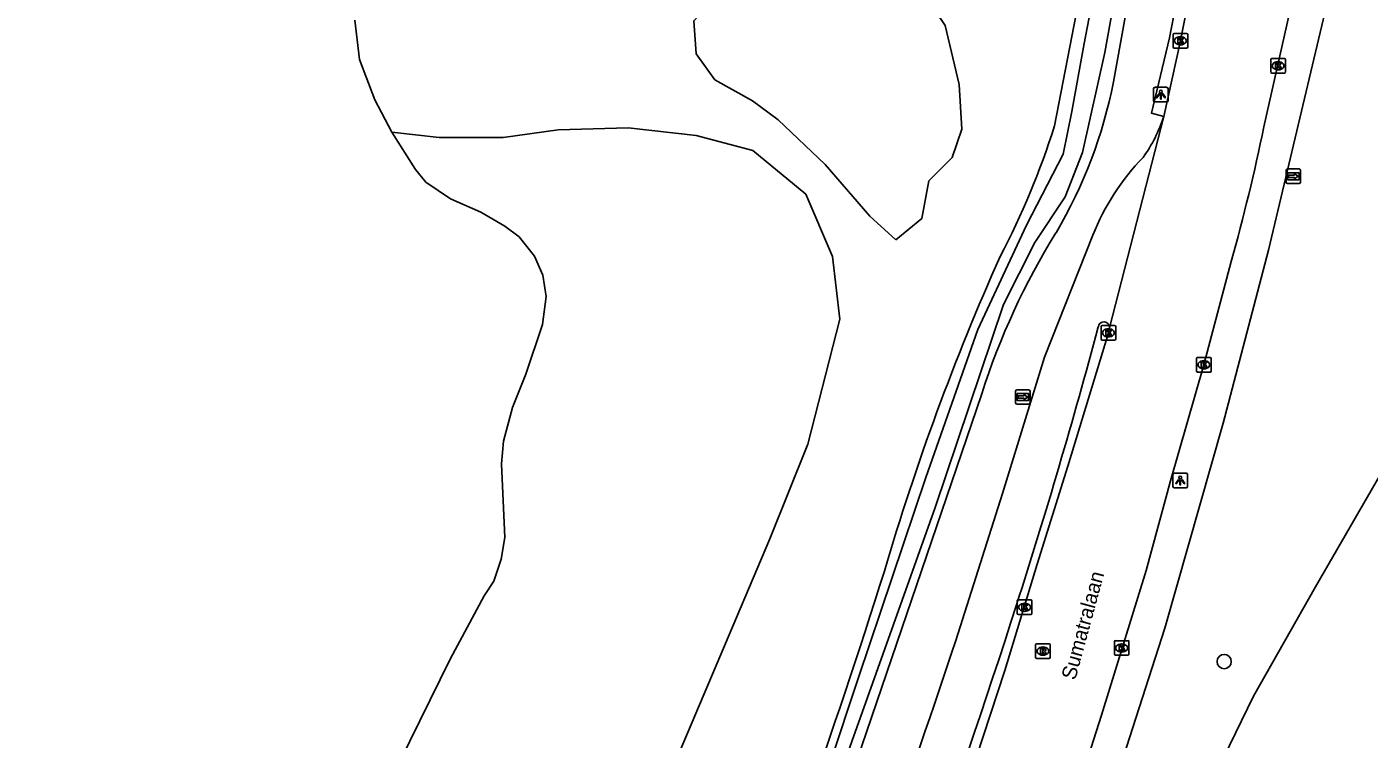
# Model space of a CAD drawing. Extents: x 162417 to 163721, y 384268 to 385416.
# Drawn here: x 162743.5 to 162835.2, y 385301.4 to 385350.1 of the extents above; entities that cross this region are included whole.
import ezdxf

# ---------------------------------------------------------------- set-up
doc = ezdxf.new("R2010")
doc.units = 0
for name, color, linetype in [('IMGEO_Boom', 7, 'Continuous'), ('IMGEO_Fietspad_gesloten', 7, 'Continuous'), ('IMGEO_Gemengd_bos', 7, 'Continuous'), ('IMGEO_Groenvoorziening', 7, 'Continuous'), ('IMGEO_Kolk', 7, 'Continuous'), ('IMGEO_Lichtpunt', 7, 'Continuous'), ('IMGEO_Loofbos', 7, 'Continuous'), ('IMGEO_Openbare_ruimte_label', 7, 'Continuous'), ('IMGEO_Rietland', 7, 'Continuous'), ('IMGEO_Rijbaan_lokaal_open', 7, 'Continuous'), ('IMGEO_Rioolput', 7, 'Continuous'), ('IMGEO_Voetpad_open', 7, 'Continuous'), ('IMGEO_Waterloop', 7, 'Continuous'), ('IMGEO_Wegwijzer', 7, 'Continuous')]:
    doc.layers.add(name, color=color, linetype=linetype)

msp = doc.modelspace()

# ---------------------------------------------------------------- linework, layer by layer
at = {"layer": 'IMGEO_Boom'}
msp.add_circle((162825.334, 385306.727), 0.489, dxfattribs=at)
at = {"layer": 'IMGEO_Fietspad_gesloten'}
msp.add_lwpolyline([(162816.367, 385335.842), (162813.052, 385327.519), (162810.185, 385318.215), (162807.009, 385308.175)], dxfattribs=at)
for centre, radius, start, end in [((162811.055, 385347.283), 10.681, 325.03841, 341.83149), ((162831.08, 385330.1), 15.794, 135.53739, 158.68249), ((162410.819, 385438.792), 420.352, 342.24558, 344.94099), ((162817.12, 385329.544), 0.385, 355.3852, 174.79122), ((162215.588, 385502.359), 625.67, 338.291039, 342.153446), ((162026.4, 385569.306), 823.128, 339.426761, 341.503782)]:
    msp.add_arc(centre, radius, start, end, dxfattribs=at)
at = {"layer": 'IMGEO_Gemengd_bos'}
msp.add_lwpolyline([(162814.913, 385263.725), (162814.61, 385265.935), (162814.59, 385269.784), (162815.131, 385272.835), (162815.951, 385276.063), (162817.275, 385280.881), (162819.108, 385286.107), (162824.458, 385298.467), (162827.331, 385304.355), (162831.573, 385311.834), (162853.395, 385349.579)], dxfattribs=at)
at = {"layer": 'IMGEO_Groenvoorziening'}
for points in [[(162817.771, 385346.314), (162823.818, 385379.783)], [(162820.255, 385376.893), (162813.74, 385343.308)], [(162743.529, 385195.341), (162794.303, 385315.112), (162796.888, 385321.578), (162799.085, 385330.113), (162798.568, 385334.381), (162796.759, 385338.648), (162793.14, 385341.623), (162789.264, 385342.657), (162784.611, 385343.175), (162779.83, 385343.045), (162776.082, 385342.528), (162771.689, 385342.528), (162768.457, 385342.888)], [(162796.119, 385287.884), (162808.773, 385325.013)]]:
    msp.add_lwpolyline(points, dxfattribs=at)
for centre, radius, start, end in [((162785.841, 385352.589), 32.541, 329.37861, 348.88148), ((162760.787, 385360.126), 55.56, 332.40245, 342.38062), ((162855.966, 385309.928), 49.546, 148.23055, 162.27401), ((162964.427, 385265.402), 169.112, 155.92544, 163.68346), ((162281.566, 385477.839), 546.061, 338.77326, 342.42056)]:
    msp.add_arc(centre, radius, start, end, dxfattribs=at)
at = {"layer": 'IMGEO_Kolk'}
for p, q in [((162821.841, 385348.7), (162821.841, 385349.552)), ((162821.916, 385349.626), (162822.768, 385349.626)), ((162822.352, 385348.846), (162822.327, 385348.846)), ((162822.329, 385349.406), (162822.354, 385349.406)), ((162822.842, 385349.552), (162822.842, 385348.7)), ((162822.768, 385348.626), (162821.916, 385348.626)), ((162828.593, 385347.917), (162829.445, 385347.917)), ((162828.518, 385346.991), (162828.518, 385347.843)), ((162829.029, 385347.137), (162829.004, 385347.137)), ((162829.006, 385347.697), (162829.031, 385347.697)), ((162829.519, 385347.843), (162829.519, 385346.991)), ((162829.445, 385346.917), (162828.593, 385346.917)), ((162816.92, 385328.752), (162816.92, 385329.604)), ((162816.995, 385329.678), (162817.847, 385329.678)), ((162817.921, 385329.604), (162817.921, 385328.752)), ((162817.847, 385328.678), (162816.995, 385328.678)), ((162817.431, 385328.898), (162817.406, 385328.898)), ((162817.408, 385329.458), (162817.433, 385329.458)), ((162823.446, 385326.573), (162823.446, 385327.425)), ((162823.521, 385327.499), (162824.373, 385327.499)), ((162823.934, 385327.279), (162823.959, 385327.279)), ((162824.447, 385327.425), (162824.447, 385326.573)), ((162824.373, 385326.499), (162823.521, 385326.499)), ((162823.957, 385326.719), (162823.932, 385326.719)), ((162811.199, 385310.008), (162811.199, 385310.86)), ((162811.274, 385310.934), (162812.126, 385310.934)), ((162811.687, 385310.714), (162811.712, 385310.714)), ((162812.2, 385310.86), (162812.2, 385310.008)), ((162812.126, 385309.934), (162811.274, 385309.934)), ((162811.71, 385310.154), (162811.685, 385310.154)), ((162817.83, 385307.23), (162817.83, 385308.082)), ((162817.905, 385308.156), (162818.757, 385308.156)), ((162818.318, 385307.936), (162818.343, 385307.936)), ((162818.831, 385308.082), (162818.831, 385307.23)), ((162818.757, 385307.156), (162817.905, 385307.156)), ((162818.341, 385307.376), (162818.316, 385307.376))]:
    msp.add_line(p, q, dxfattribs=at)
for points in [[(162821.841, 385348.7), (162821.841, 385349.552)], [(162821.916, 385349.626), (162822.768, 385349.626)], [(162822.162, 385349.326), (162822.285, 385349.326), (162822.285, 385349.175), (162822.415, 385349.326), (162822.579, 385349.326), (162822.433, 385349.175), (162822.586, 385348.926), (162822.434, 385348.926), (162822.349, 385349.09), (162822.285, 385349.023), (162822.285, 385348.926), (162822.162, 385348.926), (162822.162, 385349.326)], [(162822.842, 385349.552), (162822.842, 385348.7)], [(162822.768, 385348.626), (162821.916, 385348.626)], [(162828.593, 385347.917), (162829.445, 385347.917)], [(162828.518, 385346.991), (162828.518, 385347.843)], [(162828.839, 385347.617), (162828.962, 385347.617), (162828.962, 385347.466), (162829.092, 385347.617), (162829.256, 385347.617), (162829.11, 385347.466), (162829.263, 385347.217), (162829.111, 385347.217), (162829.026, 385347.381), (162828.962, 385347.314), (162828.962, 385347.217), (162828.839, 385347.217), (162828.839, 385347.617)], [(162829.519, 385347.843), (162829.519, 385346.991)], [(162829.445, 385346.917), (162828.593, 385346.917)], [(162816.92, 385328.752), (162816.92, 385329.604)], [(162816.995, 385329.678), (162817.847, 385329.678)], [(162817.921, 385329.604), (162817.921, 385328.752)], [(162817.847, 385328.678), (162816.995, 385328.678)], [(162817.241, 385329.378), (162817.364, 385329.378), (162817.364, 385329.227), (162817.494, 385329.378), (162817.658, 385329.378), (162817.512, 385329.227), (162817.665, 385328.978), (162817.513, 385328.978), (162817.428, 385329.142), (162817.364, 385329.075), (162817.364, 385328.978), (162817.241, 385328.978), (162817.241, 385329.378)], [(162823.446, 385326.573), (162823.446, 385327.425)], [(162823.521, 385327.499), (162824.373, 385327.499)], [(162823.767, 385327.199), (162823.89, 385327.199), (162823.89, 385327.048), (162824.02, 385327.199), (162824.184, 385327.199), (162824.038, 385327.048), (162824.191, 385326.799), (162824.039, 385326.799), (162823.954, 385326.963), (162823.89, 385326.896), (162823.89, 385326.799), (162823.767, 385326.799), (162823.767, 385327.199)], [(162824.447, 385327.425), (162824.447, 385326.573)], [(162824.373, 385326.499), (162823.521, 385326.499)], [(162811.199, 385310.008), (162811.199, 385310.86)], [(162811.274, 385310.934), (162812.126, 385310.934)], [(162811.52, 385310.634), (162811.643, 385310.634), (162811.643, 385310.483), (162811.773, 385310.634), (162811.937, 385310.634), (162811.791, 385310.483), (162811.944, 385310.234), (162811.792, 385310.234), (162811.707, 385310.398), (162811.643, 385310.331), (162811.643, 385310.234), (162811.52, 385310.234), (162811.52, 385310.634)], [(162812.2, 385310.86), (162812.2, 385310.008)], [(162812.126, 385309.934), (162811.274, 385309.934)], [(162817.83, 385307.23), (162817.83, 385308.082)], [(162817.905, 385308.156), (162818.757, 385308.156)], [(162818.151, 385307.856), (162818.274, 385307.856), (162818.274, 385307.705), (162818.404, 385307.856), (162818.568, 385307.856), (162818.422, 385307.705), (162818.575, 385307.456), (162818.423, 385307.456), (162818.338, 385307.62), (162818.274, 385307.553), (162818.274, 385307.456), (162818.151, 385307.456), (162818.151, 385307.856)], [(162818.831, 385308.082), (162818.831, 385307.23)], [(162818.757, 385307.156), (162817.905, 385307.156)]]:
    msp.add_lwpolyline(points, dxfattribs=at)
for centre, start, end in [((162821.918, 385349.55), 91.55205, 178.44795), ((162821.918, 385349.55), 91.55205, 178.44795), ((162822.766, 385349.55), 1.55205, 88.44795), ((162822.766, 385349.55), 1.55205, 88.44795), ((162821.918, 385348.702), 181.55205, 268.44795), ((162821.918, 385348.702), 181.55205, 268.44795), ((162822.766, 385348.702), 271.55205, 358.44795), ((162822.766, 385348.702), 271.55205, 358.44795), ((162828.595, 385347.841), 91.55205, 178.44795), ((162828.595, 385347.841), 91.55205, 178.44795), ((162829.443, 385347.841), 1.55205, 88.44795), ((162829.443, 385347.841), 1.55205, 88.44795), ((162828.595, 385346.993), 181.55205, 268.44795), ((162828.595, 385346.993), 181.55205, 268.44795), ((162829.443, 385346.993), 271.55205, 358.44795), ((162829.443, 385346.993), 271.55205, 358.44795), ((162816.997, 385329.602), 91.55205, 178.44795), ((162816.997, 385329.602), 91.55205, 178.44795), ((162817.845, 385329.602), 1.55205, 88.44795), ((162817.845, 385329.602), 1.55205, 88.44795), ((162816.997, 385328.754), 181.55205, 268.44795), ((162816.997, 385328.754), 181.55205, 268.44795), ((162817.845, 385328.754), 271.55205, 358.44795), ((162817.845, 385328.754), 271.55205, 358.44795), ((162823.523, 385327.423), 91.55205, 178.44795), ((162823.523, 385327.423), 91.55205, 178.44795), ((162824.371, 385327.423), 1.55205, 88.44795), ((162824.371, 385327.423), 1.55205, 88.44795), ((162823.523, 385326.575), 181.55205, 268.44795), ((162823.523, 385326.575), 181.55205, 268.44795), ((162824.371, 385326.575), 271.55205, 358.44795), ((162824.371, 385326.575), 271.55205, 358.44795), ((162811.276, 385310.858), 91.55205, 178.44795), ((162811.276, 385310.858), 91.55205, 178.44795), ((162812.124, 385310.858), 1.55205, 88.44795), ((162812.124, 385310.858), 1.55205, 88.44795), ((162811.276, 385310.01), 181.55205, 268.44795), ((162811.276, 385310.01), 181.55205, 268.44795), ((162812.124, 385310.01), 271.55205, 358.44795), ((162812.124, 385310.01), 271.55205, 358.44795), ((162817.907, 385308.08), 91.55205, 178.44795), ((162817.907, 385308.08), 91.55205, 178.44795), ((162818.755, 385308.08), 1.55205, 88.44795), ((162818.755, 385308.08), 1.55205, 88.44795), ((162817.907, 385307.232), 181.55205, 268.44795), ((162817.907, 385307.232), 181.55205, 268.44795), ((162818.755, 385307.232), 271.55205, 358.44795), ((162818.755, 385307.232), 271.55205, 358.44795)]:
    msp.add_arc(centre, 0.0765, start, end, dxfattribs=at)
for centre, major_axis, ratio, start_param, end_param in [((162822.328, 385349.126), (-0.387, 0.002), 0.722429, 4.712389, 7.853982), ((162822.353, 385349.126), (-0.39, 0.002), 0.717154, 1.570796, 4.712389), ((162829.005, 385347.417), (-0.387, 0.002), 0.722429, 4.712389, 7.853982), ((162829.03, 385347.417), (-0.39, 0.002), 0.717154, 1.570796, 4.712389), ((162817.407, 385329.178), (-0.387, 0.002), 0.722429, 4.712389, 7.853982), ((162817.432, 385329.178), (-0.39, 0.002), 0.717154, 1.570796, 4.712389), ((162823.933, 385326.999), (-0.387, 0.002), 0.722429, 4.712389, 7.853982), ((162823.958, 385326.999), (-0.39, 0.002), 0.717154, 1.570796, 4.712389), ((162811.686, 385310.434), (-0.387, 0.002), 0.722429, 4.712389, 7.853982), ((162811.711, 385310.434), (-0.39, 0.002), 0.717154, 1.570796, 4.712389), ((162818.317, 385307.656), (-0.387, 0.002), 0.722429, 4.712389, 7.853982), ((162818.342, 385307.656), (-0.39, 0.002), 0.717154, 1.570796, 4.712389)]:
    msp.add_ellipse(centre, major_axis=major_axis, ratio=ratio, start_param=start_param, end_param=end_param, dxfattribs=at)
at = {"layer": 'IMGEO_Lichtpunt'}
for p, q in [((162820.509, 385345.849), (162820.509, 385345.042)), ((162820.509, 385345.849), (162820.509, 385345.042)), ((162821.411, 385345.944), (162820.603, 385345.944)), ((162821.411, 385345.944), (162820.603, 385345.944)), ((162821.505, 385345.042), (162821.505, 385345.849)), ((162821.505, 385345.042), (162821.505, 385345.849)), ((162820.603, 385344.948), (162821.411, 385344.948)), ((162820.603, 385344.948), (162821.411, 385344.948)), ((162821.835, 385319.498), (162821.835, 385318.691)), ((162821.835, 385319.498), (162821.835, 385318.691)), ((162822.737, 385319.593), (162821.929, 385319.593)), ((162822.737, 385319.593), (162821.929, 385319.593)), ((162822.831, 385318.691), (162822.831, 385319.498)), ((162822.831, 385318.691), (162822.831, 385319.498)), ((162821.929, 385318.597), (162822.737, 385318.597)), ((162821.929, 385318.597), (162822.737, 385318.597))]:
    msp.add_line(p, q, dxfattribs=at)
for points in [[(162820.883, 385345.513), (162820.922, 385345.485), (162820.734, 385345.223), (162820.696, 385345.25), (162820.883, 385345.513)], [(162820.985, 385345.465), (162821.032, 385345.465), (162821.032, 385345.143), (162820.985, 385345.143), (162820.985, 385345.465)], [(162821.095, 385345.485), (162821.133, 385345.512), (162821.32, 385345.25), (162821.281, 385345.222), (162821.095, 385345.485)], [(162822.209, 385319.162), (162822.248, 385319.134), (162822.06, 385318.872), (162822.022, 385318.899), (162822.209, 385319.162)], [(162822.311, 385319.114), (162822.358, 385319.114), (162822.358, 385318.792), (162822.311, 385318.792), (162822.311, 385319.114)], [(162822.421, 385319.134), (162822.459, 385319.161), (162822.646, 385318.899), (162822.607, 385318.871), (162822.421, 385319.134)]]:
    msp.add_lwpolyline(points, dxfattribs=at)
for centre in [(162821.008, 385345.647), (162822.334, 385319.296)]:
    msp.add_circle(centre, 0.0994, dxfattribs=at)
for centre, start, end in [((162820.603, 385345.849), 90, 180), ((162820.603, 385345.849), 90, 180), ((162821.411, 385345.849), 0, 90), ((162821.411, 385345.849), 0, 90), ((162820.603, 385345.042), 180, 270), ((162820.603, 385345.042), 180, 270), ((162821.411, 385345.042), 270, 0), ((162821.411, 385345.042), 270, 360), ((162821.929, 385319.498), 90, 180), ((162821.929, 385319.498), 90, 180), ((162822.737, 385319.498), 0, 90), ((162822.737, 385319.498), 0, 90), ((162821.929, 385318.691), 180, 270), ((162821.929, 385318.691), 180, 270), ((162822.737, 385318.691), 270, 0), ((162822.737, 385318.691), 270, 360)]:
    msp.add_arc(centre, 0.0946, start, end, dxfattribs=at)
at = {"layer": 'IMGEO_Loofbos'}
msp.add_lwpolyline([(162802.902, 385335.53), (162801.135, 385337.138), (162798.084, 385340.674), (162794.871, 385343.728), (162793.105, 385345.013), (162790.535, 385346.46), (162789.25, 385348.228), (162789.09, 385350.478), (162791.499, 385353.05), (162795.193, 385355.461), (162799.208, 385355.943), (162802.259, 385354.657), (162804.347, 385353.05), (162806.275, 385350.157), (162807.238, 385346.138), (162807.399, 385343.085), (162806.756, 385341.156), (162805.15, 385339.548), (162804.669, 385336.977), (162802.902, 385335.53)], dxfattribs=at)
at = {"layer": 'IMGEO_Rietland'}
for points in [[(162765.937, 385350.529), (162766.247, 385347.849), (162767.294, 385345.094), (162768.457, 385342.888)], [(162768.457, 385342.888), (162770.072, 385340.336), (162770.798, 385339.473), (162772.464, 385338.333), (162774.536, 385337.422), (162776.177, 385336.473), (162777.156, 385335.738), (162778.213, 385334.419), (162778.787, 385333.111), (162779.006, 385331.663), (162778.756, 385329.757), (162777.631, 385326.362), (162776.721, 385324.074), (162776.09, 385321.773), (162775.953, 385320.223), (162776.178, 385315.192), (162775.927, 385313.717), (162775.434, 385312.217), (162774.776, 385311.225), (162772.446, 385306.901), (162769.016, 385299.906)]]:
    msp.add_lwpolyline(points, dxfattribs=at)
at = {"layer": 'IMGEO_Rijbaan_lokaal_open'}
for points in [[(162821.203, 385343.953), (162822.339, 385349.126), (162823.767, 385356.341), (162824.103, 385358.145), (162826.486, 385370.225), (162829.061, 385385.208), (162830.957, 385397.648)], [(162831.062, 385357.297), (162829.814, 385351.114), (162828.047, 385343.244)], [(162817.504, 385329.513), (162821.203, 385343.953)], [(162825.818, 385334.053), (162823.947, 385327.004), (162821.672, 385319.081), (162820.006, 385312.943), (162816.951, 385303.058), (162813.737, 385293.04), (162812.309, 385288.98), (162805.403, 385270.094), (162800.953, 385259.064)], [(162801.107, 385279.185), (162804.288, 385287.872), (162807.417, 385297.177), (162810.337, 385306.112), (162812.556, 385313.374), (162814.649, 385320.077), (162817.422, 385329.178), (162817.504, 385329.513)]]:
    msp.add_lwpolyline(points, dxfattribs=at)
msp.add_arc((162692.639, 385371.217), 138.267, 344.40794, 348.32772, dxfattribs=at)
at = {"layer": 'IMGEO_Rioolput'}
for p, q in [((162812.452, 385307.018), (162812.452, 385307.87)), ((162812.527, 385307.944), (162813.379, 385307.944)), ((162812.94, 385307.724), (162812.965, 385307.724)), ((162813.453, 385307.87), (162813.453, 385307.018)), ((162813.379, 385306.944), (162812.527, 385306.944)), ((162812.963, 385307.164), (162812.938, 385307.164))]:
    msp.add_line(p, q, dxfattribs=at)
for points in [[(162812.452, 385307.018), (162812.452, 385307.87)], [(162812.527, 385307.944), (162813.379, 385307.944)], [(162813.041, 385307.642), (162812.789, 385307.644), (162812.789, 385307.244)], [(162812.967, 385307.563), (162812.913, 385307.563), (162812.913, 385307.482)], [(162813.453, 385307.87), (162813.453, 385307.018)], [(162813.379, 385306.944), (162812.527, 385306.944)], [(162812.789, 385307.244), (162812.913, 385307.244), (162812.913, 385307.406), (162812.924, 385307.406)], [(162812.913, 385307.482), (162812.965, 385307.482)], [(162812.971, 385307.377), (162813.042, 385307.244), (162813.182, 385307.244), (162813.117, 385307.37)]]:
    msp.add_lwpolyline(points, dxfattribs=at)
for centre, radius, start, end in [((162812.529, 385307.868), 0.0765, 91.55205, 178.44795), ((162812.529, 385307.868), 0.0765, 91.55205, 178.44795), ((162812.973, 385307.467), 0.0964, 77.00612, 93.18647), ((162812.987, 385307.524), 0.0378, 276.66336, 79.67722), ((162813.04, 385307.532), 0.109, 350.36119, 89.41601), ((162813.377, 385307.868), 0.0765, 1.55205, 88.44795), ((162813.377, 385307.868), 0.0765, 1.55205, 88.44795), ((162812.529, 385307.02), 0.0765, 181.55205, 268.44795), ((162812.529, 385307.02), 0.0765, 181.55205, 268.44795), ((162812.923, 385307.353), 0.0533, 26.02933, 88.69889), ((162812.949, 385307.671), 0.19, 274.7715, 282.96867), ((162813.038, 385307.532), 0.112, 277.58423, 350.98172), ((162813.022, 385307.317), 0.108, 29.51342, 73.79051), ((162813.377, 385307.02), 0.0765, 271.55205, 358.44795), ((162813.377, 385307.02), 0.0765, 271.55205, 358.44795)]:
    msp.add_arc(centre, radius, start, end, dxfattribs=at)
for centre, major_axis, ratio, start_param, end_param in [((162812.939, 385307.444), (-0.387, 0.002), 0.722429, 4.712389, 7.853982), ((162812.964, 385307.444), (-0.39, 0.002), 0.717154, 1.570796, 4.712389)]:
    msp.add_ellipse(centre, major_axis=major_axis, ratio=ratio, start_param=start_param, end_param=end_param, dxfattribs=at)
at = {"layer": 'IMGEO_Voetpad_open'}
for points in [[(162821.203, 385343.953), (162820.376, 385344.174), (162821.604, 385349.32), (162823.339, 385358.265), (162824, 385361.752), (162823.141, 385361.941), (162824.778, 385370.372), (162827.351, 385385.013), (162829.244, 385398.075)], [(162833.912, 385359.326), (162832.652, 385352.873), (162828.354, 385334.816), (162825.269, 385323.011), (162821.278, 385309), (162814.049, 385286.612), (162811.088, 385278.427), (162805.468, 385263.839), (162799.73, 385250), (162795.245, 385240.011), (162789.813, 385229.377), (162781.721, 385213.341), (162774.899, 385200.349), (162770.222, 385192.235)]]:
    msp.add_lwpolyline(points, dxfattribs=at)
at = {"layer": 'IMGEO_Waterloop'}
for points in [[(162769.909, 385231.879), (162780.27, 385253.493), (162786.172, 385267.782), (162791.947, 385281.731), (162796.406, 385293.79), (162800.355, 385305.637), (162804.941, 385319.289), (162808.507, 385329.416), (162811.82, 385336.529), (162814.325, 385341.37), (162814.919, 385344.3), (162815.769, 385348.928), (162820.355, 385372.771)], [(162818.423, 385355.319), (162817.191, 385348.312), (162815.662, 385341.497), (162814.473, 385338.461), (162812.393, 385335.34), (162810.248, 385331.115), (162805.578, 385317.251), (162799.293, 385299.607), (162793.773, 385283.174), (162784.473, 385260.542), (162778.783, 385247.718)]]:
    msp.add_lwpolyline(points, dxfattribs=at)
at = {"layer": 'IMGEO_Wegwijzer'}
for p, q in [((162829.561, 385339.468), (162829.561, 385340.268)), ((162829.561, 385340.268), (162829.561, 385339.468)), ((162829.661, 385340.368), (162830.451, 385340.368)), ((162830.451, 385340.368), (162829.661, 385340.368)), ((162830.551, 385340.268), (162830.551, 385339.468)), ((162830.551, 385339.468), (162830.551, 385340.268)), ((162830.451, 385339.368), (162829.661, 385339.368)), ((162829.661, 385339.368), (162830.451, 385339.368)), ((162811.082, 385324.396), (162811.082, 385325.196)), ((162811.082, 385325.196), (162811.082, 385324.396)), ((162811.182, 385325.296), (162811.972, 385325.296)), ((162811.972, 385325.296), (162811.182, 385325.296)), ((162812.072, 385325.196), (162812.072, 385324.396)), ((162812.072, 385324.396), (162812.072, 385325.196)), ((162811.972, 385324.296), (162811.182, 385324.296)), ((162811.182, 385324.296), (162811.972, 385324.296))]:
    msp.add_line(p, q, dxfattribs=at)
for points in [[(162829.662, 385340.1), (162830.45, 385340.1), (162830.45, 385339.636), (162829.662, 385339.636), (162829.662, 385340.1)], [(162829.727, 385339.952), (162829.727, 385339.868), (162829.727, 385339.784), (162830.138, 385339.784), (162830.138, 385339.701), (162830.385, 385339.868), (162830.138, 385340.035), (162830.138, 385339.952), (162829.727, 385339.952)], [(162811.183, 385325.028), (162811.971, 385325.028), (162811.971, 385324.564), (162811.183, 385324.564), (162811.183, 385325.028)], [(162811.248, 385324.88), (162811.248, 385324.796), (162811.248, 385324.712), (162811.659, 385324.712), (162811.659, 385324.629), (162811.906, 385324.796), (162811.659, 385324.963), (162811.659, 385324.88), (162811.248, 385324.88)]]:
    msp.add_lwpolyline(points, dxfattribs=at)
for centre, start, end in [((162829.661, 385340.268), 90, 180), ((162829.661, 385340.268), 90, 180), ((162830.451, 385340.268), 0, 90), ((162830.451, 385340.268), 360, 90), ((162829.661, 385339.468), 180, 270), ((162829.661, 385339.468), 180, 270), ((162830.451, 385339.468), 270, 0), ((162830.451, 385339.468), 270, 0), ((162811.182, 385325.196), 90, 180), ((162811.182, 385325.196), 90, 180), ((162811.972, 385325.196), 0, 90), ((162811.972, 385325.196), 360, 90), ((162811.182, 385324.396), 180, 270), ((162811.182, 385324.396), 180, 270), ((162811.972, 385324.396), 270, 0), ((162811.972, 385324.396), 270, 0)]:
    msp.add_arc(centre, 0.1, start, end, dxfattribs=at)

# ---------------------------------------------------------------- texts
at = {"layer": 'IMGEO_Openbare_ruimte_label'}
msp.add_text('Sumatralaan', height=1, rotation=74.81021, dxfattribs=at).set_placement((162815.16, 385305.416))

doc.saveas('drawing.dxf')
